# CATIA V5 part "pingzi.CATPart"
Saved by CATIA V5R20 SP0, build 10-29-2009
Part number: Part1
Material "Alcantara": density 900 kg/m3
Bounding box of the stored display mesh (mm): x -25 to 25, y -25 to 25, z 0 to 110
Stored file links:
  I:\CATIA\pingzi.CATPart
  G:\catia v20\win_b64\startup\materials\Catalog.CATMaterial
  G:\catia v20\win_b64\startup\materials\green_env_512x512.jpg
  G:\catia v20\win_b64\startup\materials\wall_of_bricks.jpg
  G:\catia v20\win_b64\startup\materials\road.jpg
  G:\catia v20\win_b64\startup\materials\roof2.jpg
  G:\catia v20\win_b64\startup\materials\wire.png
  G:\catia v20\win_b64\startup\materials\alcantara.jpg
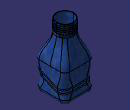
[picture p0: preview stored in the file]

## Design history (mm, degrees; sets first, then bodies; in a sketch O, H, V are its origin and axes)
Set1
  Sketch1 on xy-plane, origin (0, 0, 0), H (1, 0, 0), V (0, 1, 0)
    line L1 (25, 25) -> (25, -25)
    line L2 (25, -25) -> (-25, -25)
    line L3 (-25, -25) -> (-25, 25)
    line L4 (-25, 25) -> (25, 25)
    distance L2 L4 = 50
    distance L1 L3 = 50
    vertical: L1 V, L3 V
    horizontal: L2 H, L4 H
    equidistance: L1 L3 O, L2 L4 O
  Sketch2 on face of Pad1 from Sketch1.L1, origin (25, 0, 0), H (0, 1, 0), V (0, 0, 1)
    spline S1 through (-41.0208, 19.1785) (-23.8194, 29.3752) (5.3146, 19.1785) (39.2526, 27.8303)
  Extrude1: Element1 Sketch2, Lim1 100, Lim2 100
  MultiSel1: CommonCtxFeats ({extract ExtractElem face of Fillet1}; {extract ExtractElem face of Pad1 from Sketch1.L4}; {extract ExtractElem face of Fillet1}; {extract ExtractElem face of Pad1 from Sketch1.L3}; {extract ExtractElem face of Fillet1}; {extract ExtractElem face of Pad1 from Sketch1.L2}; {extract ExtractElem face of Fillet1}; {extract ExtractElem face of Pad1 from Sketch1.L1})
  Sketch3 on face of Pad1 from Sketch1.L3, origin (-25, 0, 0), H (0, -1, 0), V (0, 0, 1)
    spline S1 through (-29.1754, 26.7043) (-15.4565, 22.3207) (12.3331, 33.3675) (30.625, 35.121)
  Extrude2: Element1 Sketch3, Lim1 100, Lim2 100
  MultiSel2: CommonCtxFeats ({extract ExtractElem face of Pad1 from Sketch1.L3}; {extract ExtractElem face of Fillet1}; {extract ExtractElem face of Pad1 from Sketch1.L2}; {extract ExtractElem face of Fillet1}; {extract ExtractElem face of Pad1 from Sketch1.L1}; {extract ExtractElem face of Fillet1}; {extract ExtractElem face of Pad1 from Sketch1.L4}; {extract ExtractElem face of Fillet1})
  Join1: Elements ({intersect ToIntersect1 {extract ExtractElem face of Pad1 from Sketch1.L1}, ToIntersect2 Extrude2}; {intersect ToIntersect1 {extract ExtractElem face of Fillet1}, ToIntersect2 Extrude2}; {intersect ToIntersect1 {extract ExtractElem face of Pad1 from Sketch1.L4}, ToIntersect2 Extrude2}; {intersect ToIntersect1 {extract ExtractElem face of Fillet1}, ToIntersect2 Extrude2}; {intersect ToIntersect1 {extract ExtractElem face of Pad1 from Sketch1.L3}, ToIntersect2 Extrude2}; {intersect ToIntersect1 {extract ExtractElem face of Fillet1}, ToIntersect2 Extrude2}; {intersect ToIntersect1 {extract ExtractElem face of Pad1 from Sketch1.L2}, ToIntersect2 Extrude2}; {intersect ToIntersect1 {extract ExtractElem face of Fillet1}, ToIntersect2 Extrude2})
  Join2: Elements ({intersect ToIntersect1 {extract ExtractElem face of Pad1 from Sketch1.L1}, ToIntersect2 Extrude1}; {intersect ToIntersect1 {extract ExtractElem face of Fillet1}, ToIntersect2 Extrude1}; {intersect ToIntersect1 {extract ExtractElem face of Pad1 from Sketch1.L4}, ToIntersect2 Extrude1}; {intersect ToIntersect1 {extract ExtractElem face of Fillet1}, ToIntersect2 Extrude1}; {intersect ToIntersect1 {extract ExtractElem face of Pad1 from Sketch1.L3}, ToIntersect2 Extrude1}; {intersect ToIntersect1 {extract ExtractElem face of Fillet1}, ToIntersect2 Extrude1}; {intersect ToIntersect1 {extract ExtractElem face of Pad1 from Sketch1.L2}, ToIntersect2 Extrude1}; {intersect ToIntersect1 {extract ExtractElem face of Fillet1}, ToIntersect2 Extrude1})
  Plane1: type Normal, Curve Join1, RefPoint vertex [face of MultiSel2 | face of MultiSel2]
  Sketch4 on Plane1, origin (0, 7.2514, -1.4258), H (-1, 0, 0), V (0, 0.1929, 0.9812)
    circle A1 centre (-24.9405, 24.7394) radius 1
    radius A1 = 1
  Plane2: type Normal, Curve Join2, RefPoint vertex [face of MultiSel1 | face of MultiSel1]
  Sketch5 on Plane2, origin (0, 10.2539, -1.3853), H (-1, 0, 0), V (0, 0.1339, 0.991)
    circle A1 centre (-24.8669, 18.9887) radius 1
    radius A1 = 1
Body1 (main body), material "Alcantara"
  Pad1: profile Sketch1, direction (0, 0, 1), length 50
  Fillet1: on edge [face of Pad1 from Sketch1.L2 | face of Pad1 from Sketch1.L3]; edge [face of Pad1 from Sketch1.L1 | face of Pad1 from Sketch1.L2]; edge [face of Pad1 from Sketch1.L3 | face of Pad1 from Sketch1.L4]; edge [face of Pad1 from Sketch1.L4 | face of Pad1 from Sketch1.L1]
  Fillet2: radius 8, on start face of Pad1
  Plane3: type Offset, RefPlane end face of Pad1, Offset 40, reversed
  Sketch6 on Plane3, origin (0, 0, 90), H (1, 0, 0), V (0, -1, 0)
    circle A1 centre (0, 0) radius 15
    radius A1 = 15
  Pad2: profile Sketch6, direction (0, 0, -1), length -20
  Sketch7 on end face of Pad1, origin (0, 0, 50), H (1, 0, 0), V (0, 1, 0)
    point P1 (25, 0)
    distance P1 V = 25
    coincidence: P1 H
  Sketch8 on start face of Pad2, origin (0, 0, 90), H (1, 0, 0), V (0, -1, 0)
  Sketch9 on start face of Pad2, origin (0, 0, 90), H (1, 0, 0), V (0, -1, 0)
  Sketch10 on start face of Pad2, origin (0, 0, 90), H (1, 0, 0), V (0, -1, 0)
    point P1 (15, 0)
    distance P1 V = 15
    distance P1 H = 0
  Loft1: solid, Sections ({boundary Boundary {extract ExtractElem end face of Pad1}}; {boundary Boundary {extract ExtractElem start face of Pad2}}), StartFace end face of Pad1, EndFace start face of Pad2
  Slot1: profile Sketch4, centre curve Join1
  Slot2: profile Sketch5, centre curve Join2
  Shell1: IntOffset 1, Face end face of Pad2, ExtOffset 0
  Plane4: type Offset, RefPlane Plane3, Offset -2
  Sketch11 on Plane4, origin (0, 0, 92), H (1, 0, 0), V (0, -1, 0)
    point P1 (15, 0)
    distance P1 V = 15
    distance P1 H = 0
  Helix1: Direction Z axis, RefPoint Sketch11, Pitch 3, Height 16, TaperAngle 0
  Point1: type OnCurve, Support Helix1, Length 5.262
  Line1: type PtDir, RefPoint Sketch11, Direction (1, 0, 0), Start 0, End 10
  Connect1: Curve1 Line1, Point1 vertex of Line1, Tension1 1, Curve2 Helix1, Point2 Point1, Tension2 1
  Line2: type PtDir, RefPoint vertex of Helix1, Direction (0, 1, 0), Start 0, End -10
  Point2: type OnCurve, Support Connect1, Length 500.359
  Connect2: Curve1 Line2, Point1 vertex of Line2, Tension1 1, Curve2 Connect1, Point2 Point2, Tension2 1
  Plane5: type Normal, Curve Connect2, RefPoint {point type OnCurve, Support Connect2, Ratio 0}
  Sketch12 on Plane5, origin (0, 2.9904, 0), H (-1, 0, 0), V (0, 0, 1)
    circle A1 centre (7.5041, 108.0117) radius 0.5
    radius A1 = 0.5
  Rib1: profile Sketch12, centre curve Connect2
  Body2
    Sketch13 on Plane3, origin (0, 0, 90), H (1, 0, 0), V (0, -1, 0)
      circle A1 centre (0, 0) radius 14
      radius A1 = 14
    Pad3: profile Sketch13, direction (0, 0, -1), length -30
  Remove1: tool Body2
  Body3
  Remove2: tool Body3
  Body4
  Remove3: tool Body4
